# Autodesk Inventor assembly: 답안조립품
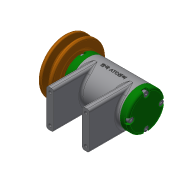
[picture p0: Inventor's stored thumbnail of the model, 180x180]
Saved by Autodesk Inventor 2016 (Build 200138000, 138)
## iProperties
Created: 2020-07
Part Number: 답안조립품
Document SubType Name: Assembly
Designer: USER
Author: USER
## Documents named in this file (15)
- C:\Users\USER\Desktop\700706V1002\답안조립품.iam
- C:\Users\USER\Desktop\700706V1002\본체.ipt
- C:\Users\USER\Desktop\700706V1002\베어링 6002.ipt
- C:\Users\USER\Desktop\700706V1002\뒤커버.ipt
- C:\Users\USER\Desktop\700706V1002\앞커버.ipt
- C:\Users\USER\Desktop\700706V1002\축.ipt
- C:\Users\USER\Desktop\700706V1002\오일 실 15 25 7.ipt
- C:\Users\USER\Desktop\700706V1002\키 3x3x12.ipt
- C:\Users\USER\Desktop\700706V1002\V벨트풀리.ipt
- C:\Users\USER\Desktop\700706V1002\와셔 8x17.ipt
- C:\Users\USER\Desktop\700706V1002\스프링와셔 8.ipt
- C:\Users\USER\Desktop\700706V1002\너트 M8.ipt
- C:\Users\USER\Desktop\700706V1002\와셔 6x11.5.ipt
- C:\Users\USER\Desktop\700706V1002\볼트 M6x8.ipt
- C:\Users\USER\Desktop\700706V1002\볼트 M4x12.ipt
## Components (1 placed, 1 different names)
1. V벨트풀리:1 — 플러쉬:2
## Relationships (1: Flush 1)
- 플러쉬:2 [Flush]: V벨트풀리:1
